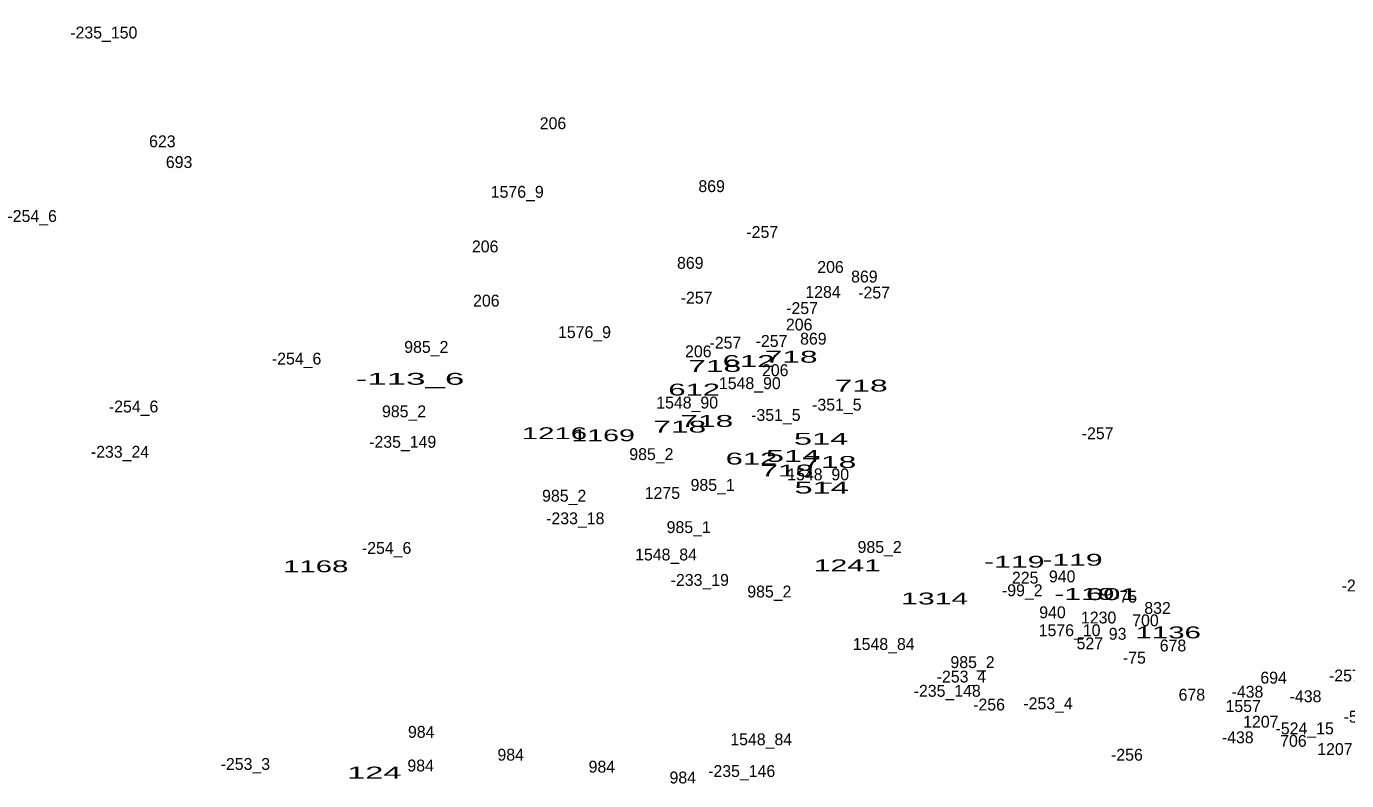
# Model space of a CAD drawing. Extents: x -660434 to -656144, y -997850 to -994016.
# Drawn here: x -659474 to -659029.2, y -994576.2 to -994322.2 of the extents above; entities that cross this region are included whole.
import ezdxf
from ezdxf.enums import TextEntityAlignment as Align

# ---------------------------------------------------------------- set-up
doc = ezdxf.new("R2010")
doc.units = 0
doc.header["$LTSCALE"] = 1.6
doc.layers.add('24', color=7, linetype='Continuous')

msp = doc.modelspace()

# ---------------------------------------------------------------- texts
at = {"layer": '24'}
for s, p in [('-235_150', (-659447.969, -994326.25)), ('206', (-659296.627, -994356.8)), ('623', (-659428.243, -994362.89)), ('693', (-659422.598, -994369.88)), ('869', (-659243.168, -994377.99)), ('1576_9', (-659308.665, -994379.9)), ('-254_6', (-659472.112, -994388.05)), ('-257', (-659226.101, -994393.43)), ('206', (-659319.477, -994398.29)), ('869', (-659250.368, -994403.83)), ('206', (-659203.117, -994405.2)), ('869', (-659191.708, -994408.44)), ('1284', (-659205.644, -994413.62)), ('-257', (-659188.431, -994413.82)), ('206', (-659319.087, -994416.54)), ('-257', (-659248.241, -994415.57)), ('-257', (-659212.701, -994419.06)), ('1576_9', (-659286.005, -994427.15)), ('206', (-659213.677, -994424.6)), ('-257', (-659238.531, -994430.71)), ('-257', (-659222.991, -994430.13)), ('869', (-659208.898, -994429.37)), ('-254_6', (-659383.012, -994436.07)), ('985_2', (-659339.31, -994432.13)), ('206', (-659247.657, -994433.63)), ('206', (-659221.737, -994439.97)), ('1548_90', (-659230.301, -994444.35)), ('-254_6', (-659437.932, -994452.2)), ('985_2', (-659346.8, -994453.83)), ('1548_90', (-659251.421, -994450.88)), ('-351_5', (-659200.986, -994451.59)), ('-351_5', (-659221.526, -994455.05)), ('-257', (-659113.111, -994461.22)), ('-233_24', (-659442.516, -994467.46)), ('-235_149', (-659347.255, -994464.1)), ('985_2', (-659263.47, -994468.24)), ('1548_90', (-659207.281, -994475.06)), ('985_1', (-659242.824, -994478.61)), ('985_2', (-659292.85, -994482.26)), ('1275', (-659259.766, -994481.32)), ('-233_18', (-659289.115, -994489.86)), ('985_1', (-659250.894, -994492.82)), ('-254_6', (-659352.682, -994499.84)), ('1548_84', (-659258.537, -994502.05)), ('985_2', (-659186.56, -994499.51)), ('-233_19', (-659247.161, -994510.61)), ('225', (-659137.527, -994509.86)), ('940', (-659125.061, -994509.43)), ('985_2', (-659223.72, -994514.52)), ('-99_2', (-659138.503, -994514.09)), ('-75', (-659103.701, -994516.24)), ('-257', (-659025.531, -994512.5)), ('832', (-659092.927, -994520.05)), ('940', (-659128.331, -994521.51)), ('1230', (-659112.784, -994523.28)), ('700', (-659097.001, -994524.21)), ('1576_10', (-659122.557, -994527.55)), ('93', (-659106.383, -994528.75)), ('1548_84', (-659185.187, -994532.21)), ('527', (-659115.733, -994531.96)), ('678', (-659087.718, -994532.7)), ('985_2', (-659155.27, -994538.3)), ('-75', (-659100.731, -994536.79)), ('-253_4', (-659159.007, -994543.16)), ('-257', (-659029.801, -994542.8)), ('694', (-659053.823, -994543.51)), ('-235_148', (-659163.789, -994547.96)), ('-253_4', (-659129.817, -994552.18)), ('678', (-659081.368, -994549.26)), ('-438', (-659062.639, -994548.26)), ('-438', (-659043.049, -994549.79)), ('-256', (-659149.7, -994552.58)), ('1557', (-659064.076, -994553.1)), ('1207', (-659058.13, -994558.36)), ('-524_15', (-659043.349, -994560.61)), ('-524_15', (-659020.409, -994556.67)), ('984', (-659341.027, -994561.79)), ('1548_84', (-659226.467, -994564.28)), ('-438', (-659065.899, -994563.62)), ('706', (-659047.152, -994564.81)), ('984', (-659310.877, -994569.47)), ('-256', (-659103.24, -994569.49)), ('1207', (-659033.17, -994567.58)), ('-253_3', (-659400.272, -994572.6)), ('984', (-659341.217, -994573.12)), ('984', (-659280.157, -994573.5)), ('984', (-659252.897, -994577.15)), ('-235_146', (-659233.045, -994574.98))]:
    msp.add_text(s, height=4, dxfattribs=at).set_placement(p, align=Align.CENTER)
for s, width, p in [('718', 2, (-659216.393, -994435.45)), ('718', 2, (-659242.123, -994438.53)), ('612', 1.95, (-659230.713, -994436.9)), ('-113_6', 2.2, (-659344.803, -994442.88)), ('718', 2, (-659192.783, -994445.15)), ('612', 1.95, (-659249.043, -994446.5)), ('718', 2, (-659244.813, -994457.06)), ('1216', 1.85, (-659296.129, -994461.2)), ('1169', 1.8, (-659279.733, -994461.89)), ('718', 2, (-659253.933, -994458.98)), ('514', 2.05, (-659206.293, -994463.07)), ('612', 1.95, (-659229.753, -994469.74)), ('514', 2.05, (-659215.743, -994468.86)), ('718', 2, (-659203.343, -994470.89)), ('718', 2, (-659217.833, -994473.77)), ('514', 2.05, (-659206.093, -994479.51)), ('1168', 1.85, (-659376.569, -994506.01)), ('1241', 1.9, (-659197.459, -994505.7)), ('-119', 1.9, (-659141.201, -994504.48)), ('-119', 1.9, (-659121.611, -994503.81)), ('-119', 1.9, (-659117.581, -994515.34)), ('601', 1.95, (-659108.359, -994515.4)), ('1314', 1.9, (-659168.009, -994516.86)), ('1136', 1.85, (-659089.329, -994528.29)), ('124', 2.05, (-659356.813, -994575.49))]:
    msp.add_text(s, height=4, dxfattribs=dict(at, width=width)).set_placement(p, align=Align.CENTER)

doc.saveas('drawing.dxf')
